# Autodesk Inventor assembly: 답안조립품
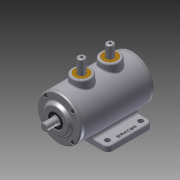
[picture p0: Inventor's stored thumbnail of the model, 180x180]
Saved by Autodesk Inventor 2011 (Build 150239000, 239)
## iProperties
Created: 2014-12
Part Number: 답안조립품
Document SubType Name: Assembly
Designer: user
Author: user
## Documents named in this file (10)
- D:\441225V1013\답안조립품.iam
- D:\441225V1013\1-본체.ipt
- D:\441225V1013\4-축.ipt
- D:\441225V1013\뒷커버.ipt
- D:\441225V1013\베어링 6203.ipt
- D:\441225V1013\부시.ipt
- D:\441225V1013\슬라이더.ipt
- D:\441225V1013\앞커버.ipt
- D:\441225V1013\오일실.ipt
- D:\441225V1013\M4-소켓머리.ipt
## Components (13 placed, 5 different names)
1. 1-본체:1
2. 4-축:1
3. 7-베어링 6203:1
4. 8-오일실:1
5. 7-베어링 6203:2
6. 9-M4-소켓머리:1
7. 9-M4-소켓머리:3
8. 9-M4-소켓머리:4
9. 9-M4-소켓머리:5
10. 9-M4-소켓머리:2
11. 9-M4-소켓머리:6
12. 9-M4-소켓머리:7
13. 9-M4-소켓머리:8
